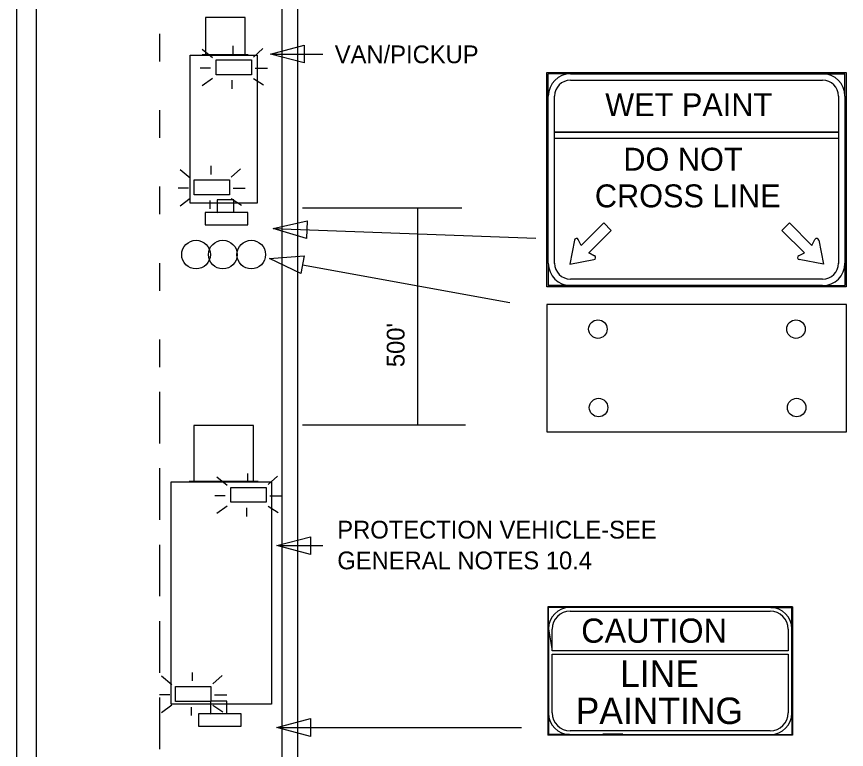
# Model space of a CAD drawing. Extents: x 1531.94 to 1538.58, y 1529.59 to 1539.32.
# Drawn here: x 1534.894 to 1537.698, y 1534.35 to 1536.828 of the extents above; entities that cross this region are included whole.
import ezdxf

# ---------------------------------------------------------------- set-up
doc = ezdxf.new("R2010")
doc.units = 0
for name, color, linetype in [('DETL-DIMS', 7, 'Continuous'), ('DETL-LINE', 7, 'Continuous'), ('DETL-NOTE', 7, 'Continuous'), ('USER-BORD', 7, 'Continuous')]:
    doc.layers.add(name, color=color, linetype=linetype)

# ---------------------------------------------------------------- blocks, each defined once
blk = doc.blocks.new('BAR')
at = {"layer": 'USER-BORD'}
for p, q in [((-0.011, 0.0696), (-0.0512, 0.1025)), ((0.0695, 0.1172), (0.0695, 0.0842)), ((0.15, 0.0732), (0.1866, 0.1062)), ((0.0037, 0.0037), (0.0037, 0.0622)), ((0.0037, 0.0622), (0.1427, 0.0622)), ((0.1427, 0.0622), (0.1427, 0.0037)), ((-0.0183, 0.0293), (-0.0585, 0.0293)), ((0.1427, 0.0037), (0.0037, 0.0037)), ((0.1573, 0.0293), (0.2049, 0.0293)), ((-0.011, -0.011), (-0.0512, -0.0403)), ((0.0658, -0.0183), (0.0658, -0.0513)), ((0.15, -0.011), (0.1902, -0.0366))]:
    blk.add_line(p, q, dxfattribs=at)
blk = doc.blocks.new('SIGN13')
at = {"layer": 'USER-BORD'}
for points in [[(-0.0134, 0.0182), (0.011, 0.0189), (0.011, 0.0371), (-0.0134, 0.0371)], [(-0.0314, 0.0182), (-0.0314, 0), (0.032, 0), (0.032, 0.0182)]]:
    blk.add_lwpolyline(points, close=True, dxfattribs=at)

msp = doc.modelspace()

# ---------------------------------------------------------------- linework, layer by layer
at = {"layer": 'DETL-DIMS'}
for p, q in [((1535.7611, 1536.7015), (1535.9286, 1536.7015)), ((1535.8604, 1536.1814), (1536.3991, 1536.1814)), ((1536.2486, 1536.1814), (1536.2486, 1535.4466)), ((1535.7611, 1536.1119), (1536.6491, 1536.0787)), ((1535.8604, 1535.9886), (1536.5606, 1535.8612)), ((1536.4116, 1535.4466), (1535.8604, 1535.4466)), ((1535.7829, 1535.0394), (1535.9286, 1535.0394)), ((1535.7829, 1534.4245), (1536.6002, 1534.4245))]:
    msp.add_line(p, q, dxfattribs=at)
for points in [[(1535.7518, 1536.7015), (1535.8656, 1536.7317), (1535.8656, 1536.6714)], [(1535.7611, 1536.1119), (1535.8759, 1536.138), (1535.8738, 1536.0778)], [(1535.7487, 1536.0101), (1535.866, 1536.0194), (1535.8552, 1535.9601)], [(1535.7736, 1535.0394), (1535.8874, 1535.0695), (1535.8874, 1535.0092)], [(1535.7736, 1534.4245), (1535.8874, 1534.4547), (1535.8874, 1534.3943)]]:
    msp.add_lwpolyline(points, close=True, dxfattribs=at)
at = {"layer": 'DETL-LINE'}
for p, q in [((1535.7908, 1538.5962), (1535.7908, 1531.7633)), ((1535.8438, 1538.5962), (1535.8438, 1531.7633)), ((1534.8945, 1538.2527), (1534.8945, 1531.7633)), ((1534.9605, 1538.2527), (1534.9605, 1531.7633)), ((1535.6668, 1536.8254), (1535.5323, 1536.8254)), ((1535.5323, 1536.8254), (1535.5323, 1536.7)), ((1535.6668, 1536.7), (1535.6668, 1536.8254)), ((1535.3789, 1536.6766), (1535.3789, 1536.7699)), ((1535.4812, 1536.1972), (1535.4812, 1536.6979)), ((1535.4812, 1536.6979), (1535.7074, 1536.6979)), ((1535.5218, 1536.7), (1535.6773, 1536.7)), ((1535.549, 1536.6979), (1535.6544, 1536.6979)), ((1535.7074, 1536.6979), (1535.7074, 1536.1972)), ((1536.6864, 1536.6391), (1537.6973, 1536.6391)), ((1536.6864, 1535.9143), (1536.6864, 1536.6391)), ((1536.766, 1536.6347), (1536.6908, 1536.6347)), ((1536.6908, 1536.5595), (1536.6908, 1536.6347)), ((1536.766, 1536.6347), (1537.6176, 1536.6347)), ((1537.6176, 1536.6347), (1537.6929, 1536.6347)), ((1537.6176, 1536.6347), (1537.6178, 1536.6347)), ((1537.6929, 1536.5595), (1537.6929, 1536.6347)), ((1537.6973, 1536.6391), (1537.6973, 1535.9143)), ((1536.766, 1536.6132), (1537.6176, 1536.6132)), ((1536.6908, 1536.5595), (1536.6908, 1536.5595)), ((1536.6908, 1535.9939), (1536.6908, 1536.5595)), ((1536.7123, 1536.4379), (1536.7123, 1536.5595)), ((1537.6714, 1536.5595), (1537.6714, 1536.4379)), ((1537.6929, 1536.5595), (1537.6929, 1535.9939)), ((1535.3789, 1536.4182), (1535.3789, 1536.5116)), ((1537.6714, 1536.4379), (1536.7123, 1536.4379)), ((1536.7123, 1536.4164), (1536.7123, 1536.4379)), ((1537.6714, 1536.4379), (1537.6714, 1536.4164)), ((1537.6714, 1536.4164), (1536.7123, 1536.4164)), ((1536.7123, 1535.9939), (1536.7123, 1536.4164)), ((1537.6714, 1536.4164), (1537.6714, 1535.9939)), ((1535.3789, 1536.1599), (1535.3789, 1536.2532)), ((1535.7074, 1536.1972), (1535.4812, 1536.1972)), ((1536.8783, 1536.1311), (1536.802, 1536.0547)), ((1536.9035, 1536.1055), (1536.8783, 1536.1311)), ((1537.4802, 1536.1055), (1537.5057, 1536.1311)), ((1537.5057, 1536.1311), (1537.5817, 1536.0547)), ((1536.8276, 1536.0295), (1536.9035, 1536.1055)), ((1537.5565, 1536.0295), (1537.4802, 1536.1055)), ((1536.779, 1536.0725), (1536.7634, 1535.991)), ((1536.802, 1536.0547), (1536.792, 1536.0743)), ((1537.5817, 1536.0547), (1537.5917, 1536.0743)), ((1537.6047, 1536.0725), (1537.6202, 1535.991)), ((1536.8276, 1536.0295), (1536.8468, 1536.0195)), ((1536.8469, 1536.0196), (1536.8276, 1536.0295)), ((1537.5368, 1536.0195), (1537.5565, 1536.0295)), ((1535.3789, 1535.9015), (1535.3789, 1535.9949)), ((1536.6908, 1535.9939), (1536.6908, 1535.9187)), ((1536.7123, 1535.994), (1536.7123, 1535.9939)), ((1536.7634, 1535.991), (1536.845, 1536.0065)), ((1537.6202, 1535.991), (1537.5387, 1536.0065)), ((1537.6929, 1535.9939), (1537.6929, 1535.9187)), ((1537.6176, 1535.9402), (1536.766, 1535.9402)), ((1537.6973, 1535.9143), (1536.6864, 1535.9143)), ((1536.766, 1535.9187), (1536.6908, 1535.9187)), ((1537.6176, 1535.9187), (1536.766, 1535.9187)), ((1537.6176, 1535.9187), (1537.6929, 1535.9187)), ((1536.6862, 1535.8544), (1536.6862, 1535.424)), ((1537.6981, 1535.8544), (1536.6862, 1535.8544)), ((1536.8548, 1535.8544), (1536.8548, 1535.8544)), ((1537.0235, 1535.8544), (1537.0235, 1535.8544)), ((1537.1921, 1535.8544), (1537.1921, 1535.8544)), ((1537.3608, 1535.8544), (1537.3608, 1535.8544)), ((1537.5294, 1535.8544), (1537.5294, 1535.8544)), ((1537.6981, 1535.424), (1537.6981, 1535.8544)), ((1535.3789, 1535.6431), (1535.3789, 1535.7365)), ((1535.3789, 1535.4659), (1535.3789, 1535.5593)), ((1535.3789, 1535.3848), (1535.3789, 1535.4781)), ((1535.6952, 1535.4461), (1535.4931, 1535.4461)), ((1535.4931, 1535.4461), (1535.4931, 1535.2578)), ((1535.6952, 1535.2578), (1535.6952, 1535.4461)), ((1536.6862, 1535.424), (1537.6981, 1535.424)), ((1535.3789, 1535.2076), (1535.3789, 1535.3009)), ((1535.4165, 1534.5029), (1535.4165, 1535.2548)), ((1535.4165, 1535.2548), (1535.756, 1535.2548)), ((1535.4774, 1535.2578), (1535.7109, 1535.2578)), ((1535.5182, 1535.2548), (1535.6766, 1535.2548)), ((1535.756, 1535.2548), (1535.756, 1534.5029)), ((1535.3789, 1535.1265), (1535.3789, 1535.2198)), ((1535.3789, 1534.9492), (1535.3789, 1535.0426)), ((1535.3789, 1534.8681), (1535.3789, 1534.9615)), ((1536.6891, 1534.8329), (1536.6891, 1534.3983)), ((1537.5164, 1534.8329), (1536.6891, 1534.8329)), ((1537.5164, 1534.8329), (1537.5164, 1534.3983)), ((1536.763, 1534.8304), (1536.6916, 1534.8304)), ((1536.6916, 1534.7587), (1536.6916, 1534.8304)), ((1537.4423, 1534.8304), (1536.763, 1534.8304)), ((1536.7651, 1534.8181), (1537.4402, 1534.8181)), ((1537.4423, 1534.8304), (1537.5137, 1534.8304)), ((1537.5137, 1534.7587), (1537.5137, 1534.8304)), ((1535.3789, 1534.6909), (1535.3789, 1534.7842)), ((1536.6916, 1534.7587), (1536.6916, 1534.4725)), ((1536.6916, 1534.7587), (1536.7038, 1534.6833)), ((1536.7038, 1534.6833), (1536.7038, 1534.7565)), ((1537.5014, 1534.7565), (1537.5014, 1534.6833)), ((1537.5137, 1534.4725), (1537.5137, 1534.7587)), ((1537.5137, 1534.7587), (1537.5137, 1534.4725)), ((1535.3789, 1534.6097), (1535.3789, 1534.7031)), ((1537.5014, 1534.6833), (1536.7038, 1534.6833)), ((1536.7038, 1534.6723), (1537.5014, 1534.6723)), ((1536.7038, 1534.4743), (1536.7038, 1534.6723)), ((1537.5014, 1534.6723), (1537.5014, 1534.4743)), ((1535.3789, 1534.4325), (1535.3789, 1534.5259)), ((1535.756, 1534.5029), (1535.4165, 1534.5029)), ((1536.6916, 1534.4725), (1536.6916, 1534.4008)), ((1537.5137, 1534.4725), (1537.5137, 1534.4008)), ((1535.3789, 1534.3514), (1535.3789, 1534.4447)), ((1537.4402, 1534.4131), (1536.7651, 1534.4131)), ((1537.5164, 1534.3983), (1536.6891, 1534.3983)), ((1536.763, 1534.4008), (1536.6916, 1534.4008)), ((1536.763, 1534.4008), (1537.4423, 1534.4008)), ((1536.8751, 1534.4033), (1536.9422, 1534.4033)), ((1537.4423, 1534.4008), (1537.5137, 1534.4008))]:
    msp.add_line(p, q, dxfattribs=at)
msp.add_lwpolyline([(1536.7123, 1536.4379), (1537.6714, 1536.4379), (1537.6714, 1536.4164), (1536.7123, 1536.4164)], close=True, dxfattribs=at)
for centre, radius in [((1535.5007, 1536.0236), 0.0484), ((1535.5912, 1536.0236), 0.0484), ((1535.6873, 1536.0236), 0.0484), ((1536.8585, 1535.7715), 0.0313), ((1537.5277, 1535.7715), 0.0313), ((1536.8608, 1535.5063), 0.0313), ((1537.53, 1535.5063), 0.0313)]:
    msp.add_circle(centre, radius, dxfattribs=at)
for centre, radius, start, end in [((1536.7661, 1536.5594), 0.0752, 90, 180), ((1537.6177, 1536.5594), 0.0752, 0, 90), ((1536.766, 1536.5595), 0.0537, 90, 180), ((1537.6178, 1536.5595), 0.0537, 0, 90), ((1536.7859, 1536.0711), 0.00703, 27, 169.2603), ((1537.5979, 1536.0711), 0.00703, 10.7397, 153), ((1536.8437, 1536.0133), 0.00703, 280.7397, 63), ((1537.5401, 1536.0133), 0.00703, 117, 259.2603), ((1536.7661, 1535.9941), 0.0752, 180, 270), ((1536.766, 1535.994), 0.0537, 180, 270), ((1537.6177, 1535.9941), 0.0752, 270, 0), ((1537.6178, 1535.994), 0.0537, 270, 0), ((1536.7631, 1534.7587), 0.0716, 90, 180), ((1536.7652, 1534.7567), 0.0613, 90, 180), ((1537.4402, 1534.7567), 0.0613, 0, 90), ((1537.4422, 1534.7587), 0.0716, 0, 90), ((1536.7631, 1534.4725), 0.0716, 180, 270), ((1536.7652, 1534.4745), 0.0613, 180, 270), ((1537.4402, 1534.4745), 0.0613, 270, 0), ((1537.4422, 1534.4725), 0.0716, 270, 0)]:
    msp.add_arc(centre, radius, start, end, dxfattribs=at)

# ---------------------------------------------------------------- block references
for name, p, xscale, yscale in [('BAR', (1535.5653, 1536.6285), 0.8611764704, 0.8611764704), ('BAR', (1535.4907, 1536.2223), 0.8611764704, 0.8611764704), ('SIGN13', (1535.6032, 1536.1239), 2.2788864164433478, 2.2788864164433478), ('BAR', (1535.615, 1535.1827), 0.8611764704, 0.8611764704), ('BAR', (1535.428, 1534.5093), 0.8611764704, 0.8611764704), ('SIGN13', (1535.5802, 1534.4291), 2.2788864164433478, 2.2788864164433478)]:
    msp.add_blockref(name, p, dxfattribs=dict(at, xscale=xscale, yscale=yscale))

# ---------------------------------------------------------------- texts
for s, p in [('WET PAINT', (1536.8832, 1536.4917)), ('DO NOT', (1536.9444, 1536.3072)), ('CROSS LINE', (1536.8482, 1536.1832))]:
    msp.add_text(s, height=0.0775, dxfattribs=at).set_placement(p)
for s, height, p in [('CAUTION', 0.08184, (1536.8021, 1534.7111)), ('LINE', 0.08948, (1536.9338, 1534.5617)), ('PAINTING', 0.08948, (1536.7835, 1534.4362))]:
    msp.add_text(s, height=height, rotation=0.0085, dxfattribs=at).set_placement(p)
at = {"layer": 'DETL-NOTE'}
for s, p in [('VAN/PICKUP', (1535.9695, 1536.6705)), ('PROTECTION VEHICLE-SEE', (1535.978, 1535.0635)), ('GENERAL NOTES 10.4', (1535.978, 1534.9595))]:
    msp.add_text(s, height=0.06, dxfattribs=at).set_placement(p)
msp.add_text("500'", height=0.06, rotation=90, dxfattribs=at).set_placement((1536.2052, 1535.643))

doc.saveas('drawing.dxf')
